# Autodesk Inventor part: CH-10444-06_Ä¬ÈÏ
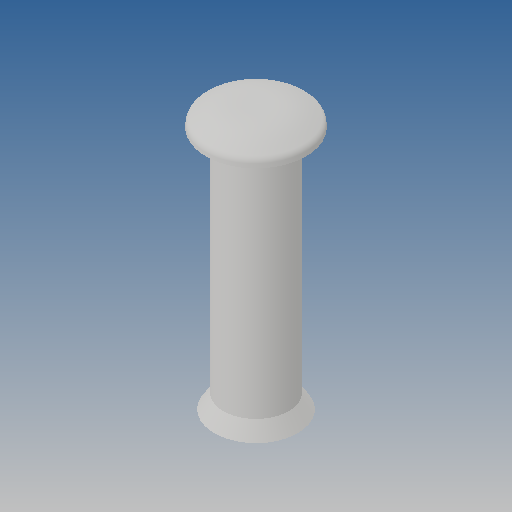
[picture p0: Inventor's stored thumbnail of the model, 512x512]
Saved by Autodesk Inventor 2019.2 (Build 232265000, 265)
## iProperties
Created: 2010-06
Part Number: CH-10444-06_Ä¬ÈÏ
Material: Ogólny
Document SubType Name: Modeling
Designer: CADENGINEERING4
Density: 1 g/cm^3
Appearance: Domyślna
Author: CADENGINEERING4
Revision Number: ÈÎºÎ
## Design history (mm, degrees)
feature "NONE"
node "Bryła1"
